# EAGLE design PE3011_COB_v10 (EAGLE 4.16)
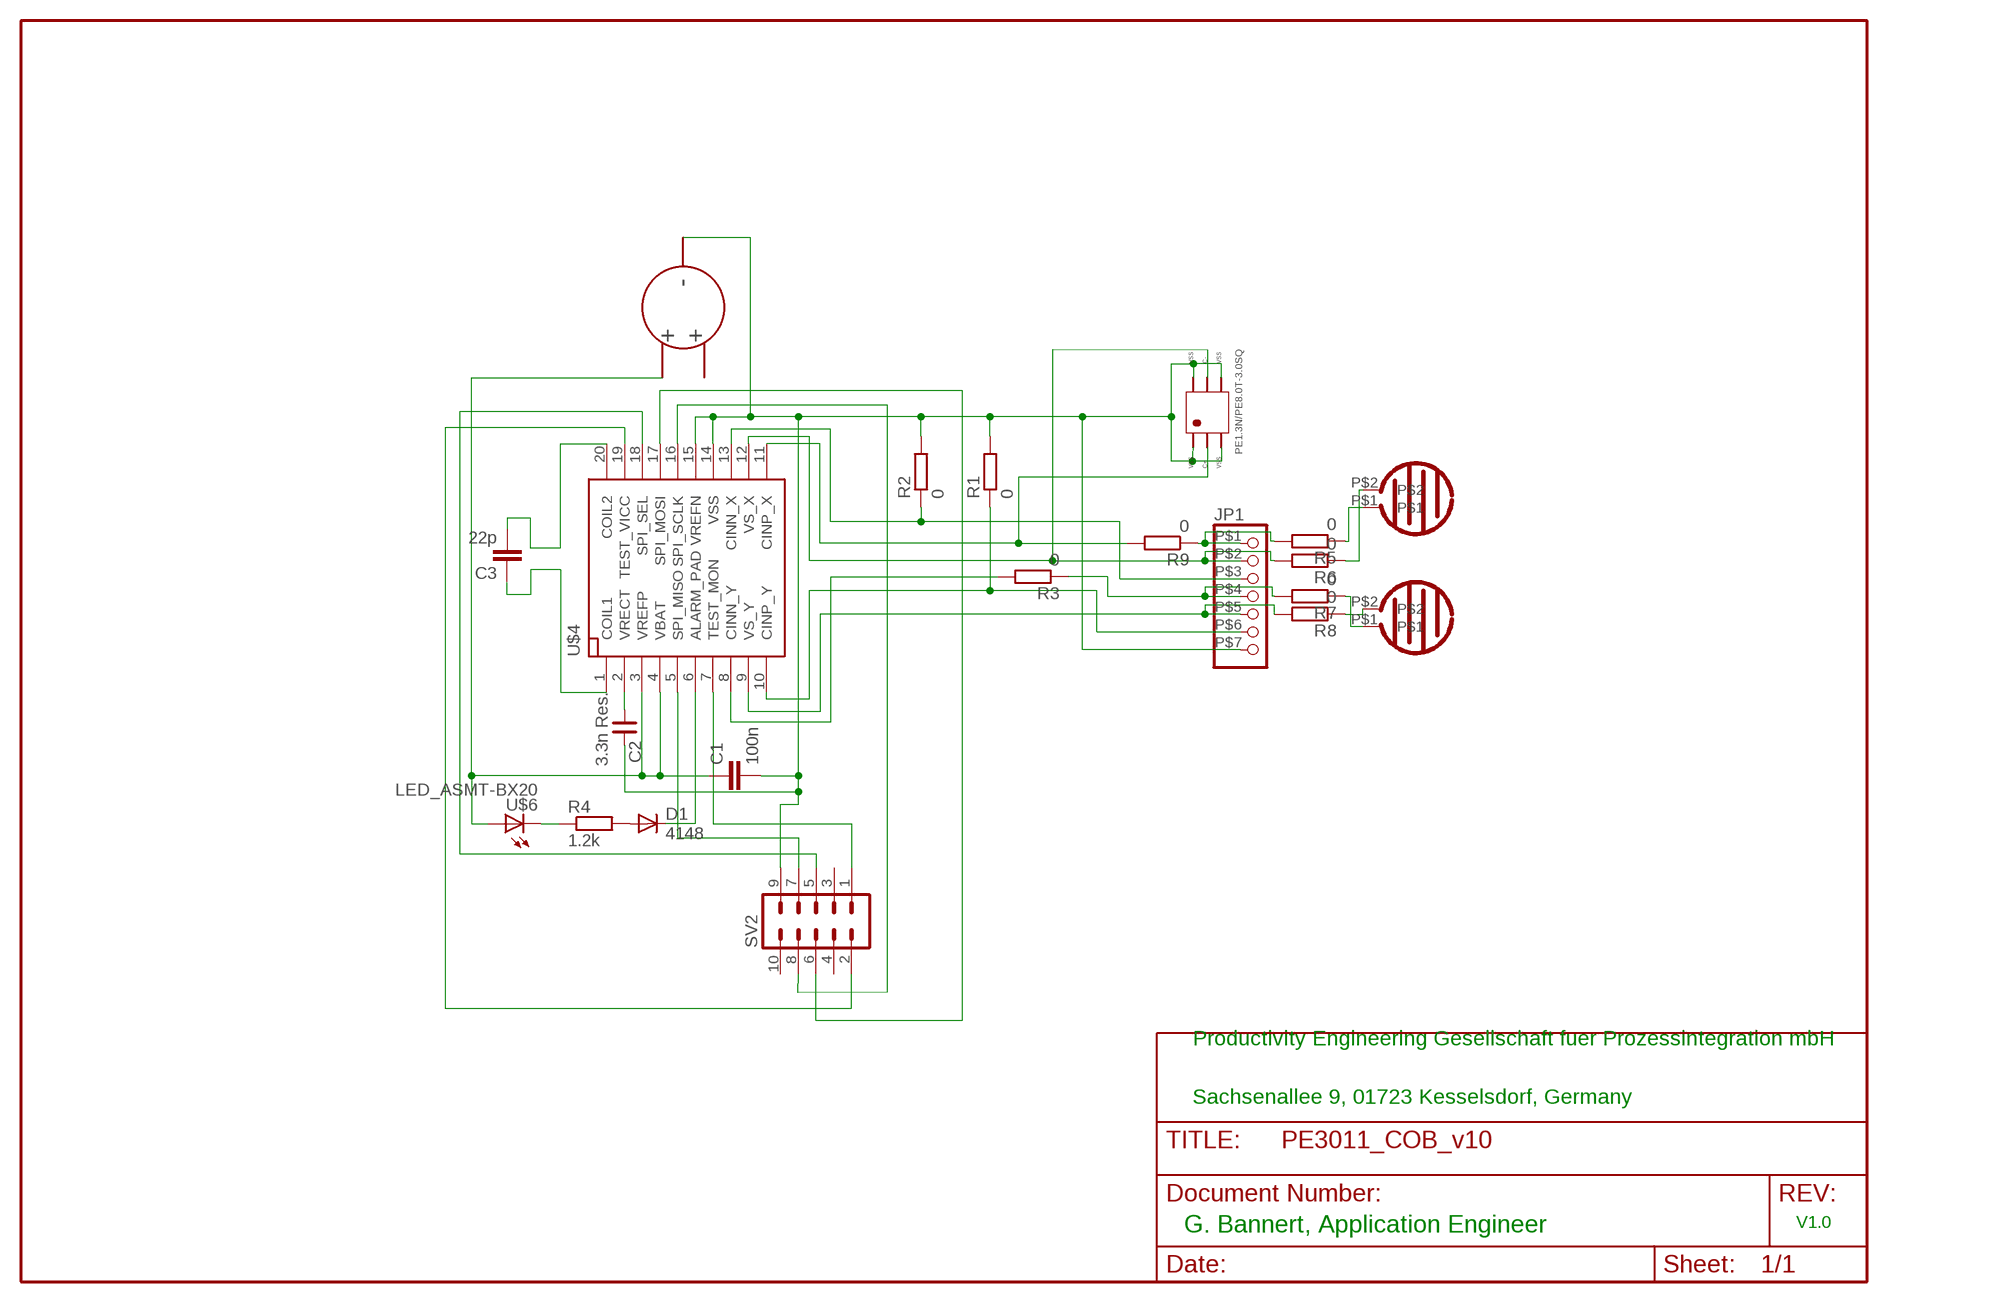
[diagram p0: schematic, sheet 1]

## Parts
C1  100n  C-EUC0805  [C0805]
C2  3.3n Res.  CNP-0402  [0402]
C3  22p  C-EUC0805  [C0805]
D1  4148  DIODE-SOD323-W  [SOD323-W]
JP1  PINHD-1X72MM  [1X07]
R1  0  R-EU_R0402  [R0402]
R2  0  R-EU_R0402  [R0402]
R3  0  R-EU_R0402  [R0402]
R4  1.2k  R-EU_R0805  [R0805]
R5  0  R-EU_R0402  [R0402]
R6  0  R-EU_R0402  [R0402]
R7  0  R-EU_R0402  [R0402]
R8  0  R-EU_R0402  [R0402]
R9  0  R-EU_R0402  [R0402]
SV2  MA05-2  [MA05-2]
U$1  TOUCH_CAP  [TOUCH_SENS]
U$2  TOUCH_CAP  [TOUCH_SENS]
U$3  MICROFAB_PRESSURESENSOR  [MICROFAB_PRESSURESENSOR]
U$4  PE3011_TSSOP20  [TSSOP20]
U$5  3002TR  [3002TR]
U$6  LED_ASMT-BX20  [LED_ASMT]

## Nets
N$1: JP1.P$2 R6.2 U$3.C- U$4.12(VS_X)
N$2: JP1.P$4 R3.1 R7.2
N$3: D1.A R4.2
N$4: R5.1 U$2.P$1
N$5: JP1.P$3 R2.1 U$4.13(CINN_X)
N$6: C3.1 U$4.1(COIL1)
N$7: R9.2 U$3.C+ U$4.11(CINP_X)
N$8: R6.1 U$2.P$2
N$9: C2.1 U$4.2(VRECT)
N$11: C1.1 U$4.3(VREFP) U$4.4(VBAT) U$5.POS_1 U$6.A
N$12: JP1.P$6 R1.1 U$4.10(CINP_Y)
N$13: SV2.5 U$4.18(SPI_SEL)
N$14: C3.2 U$4.20(COIL2)
N$15: JP1.P$1 R5.2 R9.1
N$16: SV2.2 U$4.19(TEST_VICC)
N$19: C1.2 C2.2 JP1.P$7 R1.2 R2.2 SV2.9 U$3.C_S1(CS_4) U$3.C_S2(C_S1) U$3.C_S3(C_S2) U$3.C_S4(C_S3) U$4.14(VSS) U$4.15(VREFN) U$5.NEG
N$21: SV2.7 U$4.5(SPI_MISO)
N$23: SV2.8 U$4.16(SPI_SCLK)
N$24: SV2.6 U$4.17(SPI_MOSI)
N$26: SV2.1 U$4.7(TEST_MON)
N$27: R4.1 U$6.C
N$28: D1.C U$4.6(ALARM_PAD)
N$35: R7.1 U$1.P$1
N$37: R8.1 U$1.P$2
N$38: R3.2 U$4.8(CINN_Y)
N$47: JP1.P$5 R8.2 U$4.9(VS_Y)
Unconnected: SV2.3 SV2.4 SV2.10 U$5.POS_2

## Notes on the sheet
- Productivity Engineering Gesellschaft fuer Prozessintegration mbH
- Sachsenallee 9, 01723 Kesselsdorf, Germany
- G. Bannert, Application Engineer | V1.0

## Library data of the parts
C1 C3 = rcl:C-EU: CAPACITOR, European symbol
C2 = cap-master:CNP-: NON-POLARIZED CAP
D1 = diode-1:DIODE-: DIODE
JP1 = PE5010:PINHD-1X7: PIN HEADER
R1-R9 = rcl:R-EU_: RESISTOR, European symbol
SV2 = con-lstb:MA05-2: PIN HEADER
U$1 U$2 = MeC_Bib:TOUCH_CAP
U$3 = MeC_Bib:MICROFAB_PRESSURESENSOR
U$4 = MeC_Bib:PE3011_TSSOP20
U$5 = MeC_Bib:3002TR
U$6 = MeC_Bib:LED_ASMT-BX20

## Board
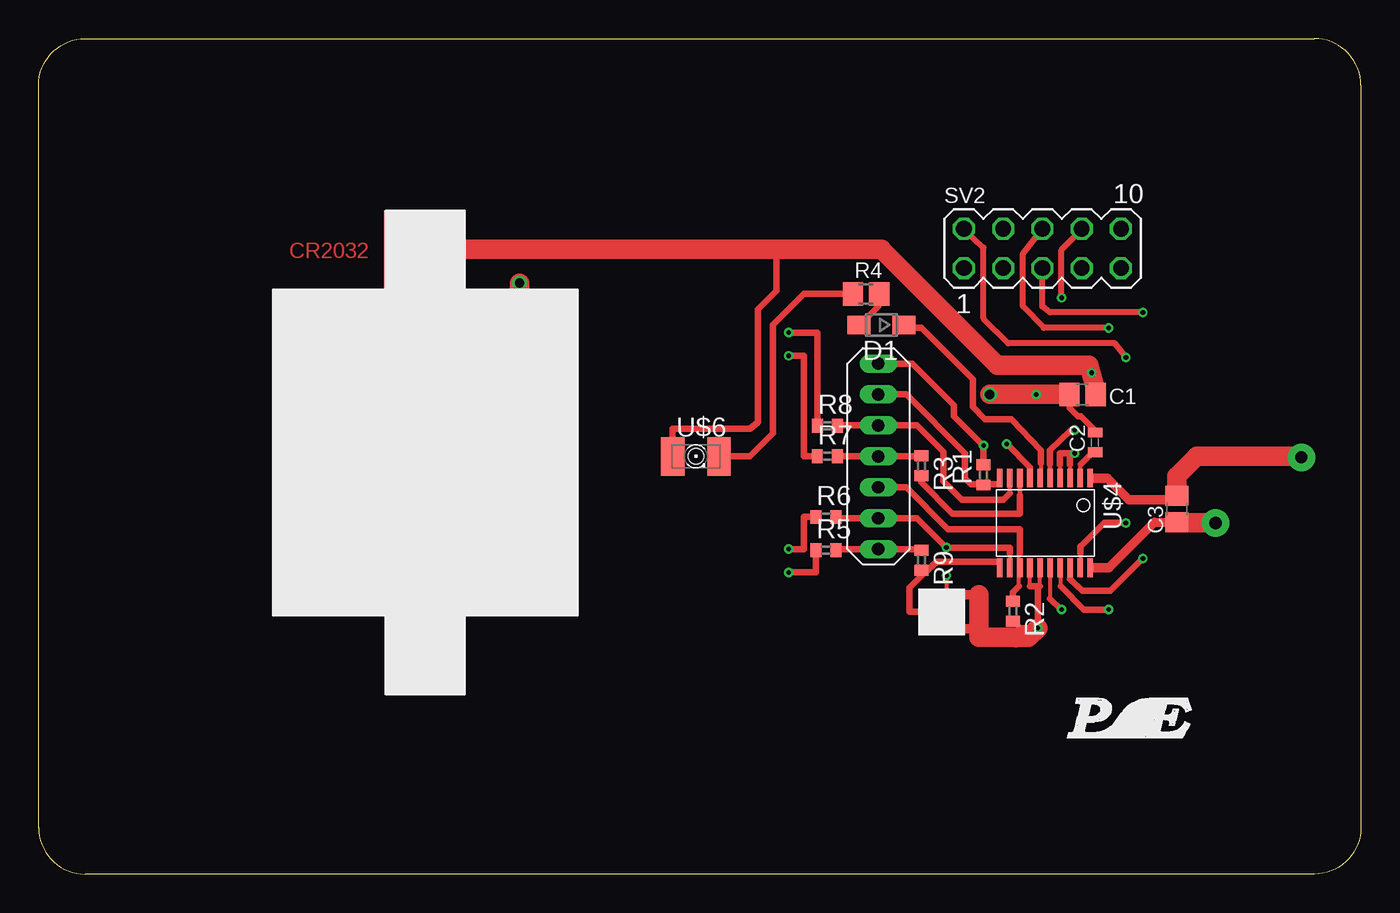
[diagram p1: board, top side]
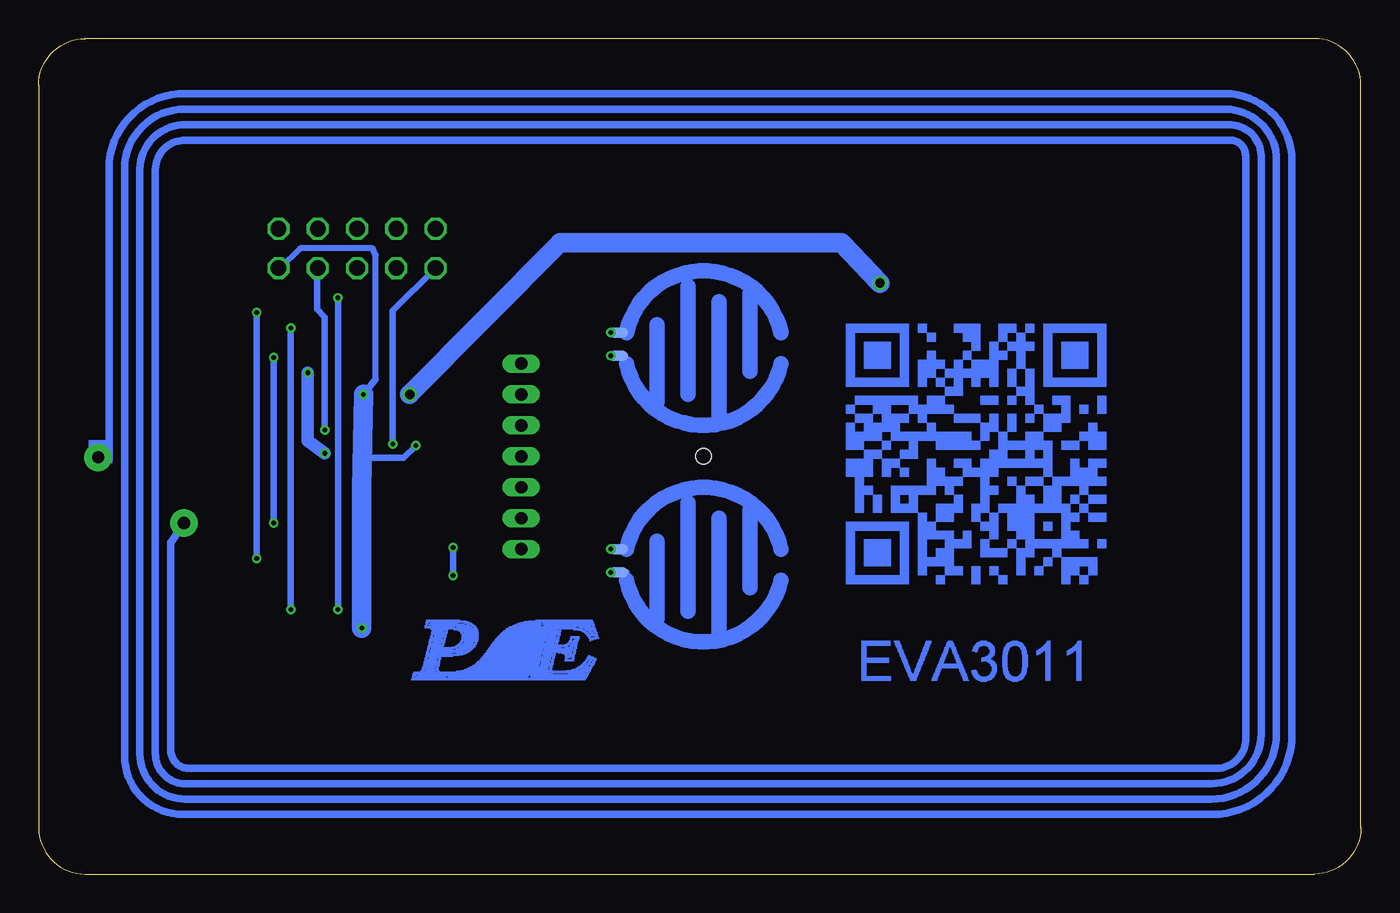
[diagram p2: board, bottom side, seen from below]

Size 85.5 x 54 mm. Coordinates in mm from the lower left corner, seen from the top.
Outline: 0,3 0,51 arc-90 3,54 82.5,54 arc-90 85.5,51 85.5,3 arc-90 82.5,0 3,0 arc-90 0,3
Copper layers (1*16): Top 0.035mm / dielectric 1.5mm / Bottom 0.035mm
Design rules "PCB-POOL": minimum track width 6mil, minimum drill 12mil, track to track 6mil, track to pad 6mil, pad to pad 6mil, via to via 6mil, smd to smd 6mil, copper to edge 20mil, drill to drill 8mil, minimum pad ring 8mil, minimum via ring 6mil, stop-mask expansion 3mil, vias tented up to drill 0mil, thermal gap 8mil
Holes 1 mm at 42.5,27

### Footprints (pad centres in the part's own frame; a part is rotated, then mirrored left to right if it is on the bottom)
C0805 = smd 1.3 x 1.5: 1 -0.85,0; 2 0.85,0
0402 = smd 0.635 x 0.94: 1 -0.635,0; 2 0.635,0
SOD323-W = smd 1.5 x 1.2: A 1.45,0; C -1.45,0
1X07 = drill 0.8 long: P$1 1,2; P$2 3,2; P$3 5,2; P$4 7,2; P$5 9,2; P$6 11,2; P$7 13,2
R0402 = smd 0.7 x 0.9: 1 -0.65,0; 2 0.65,0
R0805 = smd 1.3 x 1.5: 1 -0.85,0; 2 0.85,0
MA05-2 = drill 1.016 octagon: 1 -5.08,-1.27; 2 -5.08,1.27; 3 -2.54,-1.27; 4 -2.54,1.27; 5 0,-1.27; 6 0,1.27; 7 2.54,-1.27; 8 2.54,1.27; 9 5.08,-1.27; 10 5.08,1.27
TOUCH_SENS = smd 1.27 x 0.635: P$1 5.5,0.5; P$2 5.5,-1
MICROFAB_PRESSURESENSOR = smd 0.75 x 0.6: C+ 0.475,1.5; C- 2.525,1.5; C_S2 0.475,0.4; C_S3 2.525,0.4; C_S4 2.525,2.6 | smd 1.4 x 0.6: C_S1 0.8,2.6
TSSOP20 = smd 1.2 x 0.36: 1 -2.9,2.9; 2 -2.9,2.25; 3 -2.9,1.6; 4 -2.9,0.95; 5 -2.9,0.3; 6 -2.9,-0.35; 7 -2.9,-1; 8 -2.9,-1.65; 9 -2.9,-2.3; 10 -2.9,-2.95; 11 2.9,-2.95; 12 2.9,-2.3; 13 2.9,-1.65; 14 2.9,-1; 15 2.9,-0.35; 16 2.9,0.3; 17 2.9,0.95; 18 2.9,1.6; 19 2.9,2.25; 20 2.9,2.9
3002TR = smd 5 x 5: NEG 15.6,9.9 | smd 5.1 x 5.1: POS_1 2.56,9.79; POS_2 28.76,9.89
LED_ASMT = smd 1.5 x 2.5: A -1.5,0; C 1.5,0

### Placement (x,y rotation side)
C1  67.5,31 180 top
C2  68.31,27.91 90 top
C3  73.6,23.6 270 top
D1  54.5,35.5 180 top
JP1  56.3,20 90 top
R1  61.1,25.8 90 top
R2  62.99,16.99 270 top
R3  57.09,26.39 270 top
R4  53.5,37.5 0 top
R5  50.91,20.93 0 top
R6  50.91,23.08 0 top
R7  51,27 0 top
R8  51.01,28.98 0 top
R9  57.09,20.29 270 top
SV2  64.91,40.44 0 top
U$1  42.5,34 180 bottom
U$2  42.5,20 180 bottom
U$3  56.9,15.45 0 top
U$4  65.1,22.7 270 top
U$5  15.1,42.9 270 top
U$6  42.5,27 0 top

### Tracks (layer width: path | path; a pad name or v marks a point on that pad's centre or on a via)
N$1  (via drill 0.3)
  Top 0.2: U$3.C- 59.25,16.95 58.7,17.5
  Top 0.254: v58.7,19.3 58.7,17.5 | 62.8,20.75 U$4.12
  Top 0.406: R6.2 51.56,23 JP1.P$2 56.8,23 v58.7,21.1 62.8,21.1 62.8,20.75
  Bottom 0.406: v58.7,21.1 v58.7,19.3
N$2
  Top 0.406: 57.09,27 57.1,27 | 57.09,27 R3.1 | 54.5,27 57.09,27 | 54.5,27 JP1.P$4 | R7.2 54.5,27
N$3
  Top 0.406: D1.A 53.07,35.3 53,35.4 54.3,36.7 R4.2
N$4  (via drill 0.3)
  Top 0.406: R5.1 50.26,19.5 v48.5,19.5
  Bottom 0.406: 47.5,19.5 U$2.P$1 v48.5,19.5
N$5
  Top 0.254: 63.4,18.6 63.4,19.8 | 63.4,19.8 U$4.13 63.5,19.8 | 63.4,19.8 63.4,22.3 | 63,17.6 62.99,17.6 R2.1
  Top 0.406: JP1.P$3 56.1,25 58.8,22.3 63.4,22.3 63.45,22.3 63.45,20.75 | 63.4,18.6 63,18.2 63,17.6
N$6
  Top 0.2: 73.5,24.2 73.63,24.33 C3.1
  Top 0.305: U$4.1 68.2,25.6 | 69.05,25.6 69.1,25.6
  Top 0.61: 69.1,25.6 70.5,24.2 73.5,24.2 | 68.2,25.6 69.05,25.6
  Top 1.27: C3.1 73.6,25.7 74.9,27 81.8,27
N$7
  Top 0.254: U$4.11 62.1,19.8 62,20.2
  Top 0.406: 62,20.2 58.1,20.2 57.3,19.5 | U$3.C+ 56.3,16.95 56.3,18.5 57.3,19.5 | R9.2 57.25,19.5 57.3,19.5
N$8  (via drill 0.3)
  Top 0.406: R6.1 49.5,23.08 49.5,21 v48.5,21
  Bottom 0.406: 47.5,21 U$2.P$2 v48.5,21
N$9
  Top 0.254: C2.1 68.21,27.2 68.2,27.2 67.95,27.05 67.35,26.35 U$4.2
  Top 0.406: 67.95,27.05 67.4,26.5
N$11  (via drill 0.3)
  Top 0.254: 66.7,26.45 U$4.3 | 66.05,27.2 U$4.4
  Top 0.406: 47.7,40.4 47.7,37.7 46.5,36.5 46.5,29.2 46,28.8 41,28.8 U$6.A | 66.7,27.2 66.05,27.2 66.05,26.45 | v67,27.2 66.7,27.2 | 68.1,32.2 v68.1,32.4 | 66.7,27.2 66.7,26.45
  Top 1.27: U$5.POS_1 24.9,40.4 47.7,40.4 54.5,40.4 62,32.9 67.9,32.9 68.1,32.2 68.34,31.39 68.35,30.84 C1.1
  Bottom 0.813: v67,27.2 68.1,28 v68.1,32.4
N$12
  Top 0.254: 61.11,25.2 R1.1
  Top 0.305: 61.11,25.2 61.4,25.2 | 62.1,25.2 62.15,25.2 U$4.10
  Top 0.406: JP1.P$6 56.1,31 59.9,27.2 59.9,25.6 60.3,25.2 61.11,25.2 | 61.4,25.2 62.1,25.2
N$13  (via drill 0.3)
  Top 0.2: 64.9,39.2 64.91,39.19 SV2.5
  Top 0.254: 67.6,18.3 66.7,19.2 U$4.18
  Top 0.4: 64.9,39.2 64.9,36.7 65.4,36.3 v71.4,36.3
  Top 0.406: v71.4,20.4 69.3,18.3 67.6,18.3
  Bottom 0.406: v71.4,20.4 v71.4,36.3
N$14  (via drill 0.8 pad 1.78)
  Top 0.2: 73.7,22.7 73.7,22.8
  Top 0.305: U$4.20 68.15,19.8
  Top 0.61: 73.7,22.7 72.15,22.75 69.2,19.8 68.15,19.8
  Top 1.27: C3.2 73.7,22.7 arc2 v76.1,22.7
  Bottom 0.5: v76.1,22.7 76.85,21.55
N$15
  Top 0.406: 54.5,21 JP1.P$1 51.56,21 | 57.29,21 57.3,21 | 57.29,21 R9.1 | R5.2 51.56,21 | 51.56,21 57.29,21
N$16  (via drill 0.3)
  Top 0.2: 59.8,41.7 59.81,41.71 SV2.2
  Top 0.254: U$4.19 67.35,19.9 67.4,19.9 67.4,21.2
  Top 0.4: 59.8,41.7 61.1,40.5 61.1,35.9 62.7,34.3 69.6,34.3 v70.3,33.4
  Top 0.406: v70.3,22.7 68.9,22.7 67.4,21.2 67.35,21.2 67.35,20.75
  Bottom 0.406: v70.3,22.7 v70.3,33.4
N$19  (via drill 0.3, 0.6)
  Top 0.2: 57.38,15.88 U$3.C_S2 58.3,16.5 | 59.4,18.05 59.42,18.02 U$3.C_S4 | U$3.C_S1 58.3,18 58.3,16.5 | U$3.C_S3 59.4,15.8 58.3,16.5
  Top 0.254: 64.75,18.6 U$4.15 | 64.1,18.6 U$4.14
  Top 0.305: 63.1,16.3 63.1,16.34 R2.2
  Top 0.406: 64.5,18.6 64.1,18.6 | 64.5,18.6 64.75,18.6 | JP1.P$7 56.5,33 59.2,30.3 59.2,29.6 v61.1,27.7 R1.2 | 63.1,16.3 63.5,15.9 v64.6,15.9 64.6,18.6 64.5,18.6 | C2.2 68.21,28.79 67.4,29.6 67.2,29.6 66.7,30.1 66.7,31 C1.2
  Top 0.61: 60.8,18.05 59.4,18.05 | 60.8,15.85 U$3.C_S3
  Top 1.27: U$5.NEG 31.11,30.61 v31.1,38.2 | 60.8,15.85 60.8,18.05 60.8,15.3 63,15.3 63.18,15.28 64,15.3 v64.6,15.9 | C1.2 v64.5,31 v61.5,31
  Bottom 0.2: 69.93,39.17 SV2.9 | 64.6,24.9 64.3,24.9
  Bottom 0.4: 69.93,39.17 68.6,40.45 63.9,40.45 63.7,40 63.7,32
  Bottom 0.406: v64.5,31 63.7,32 | v61.1,27.7 61.9,26.9 64.3,26.9 64.3,24.9
  Bottom 1.27: v64.6,15.9 64.6,24.9 v64.5,31 | v31.1,38.2 33.6,40.8 51.8,40.8 v61.5,31
N$21  (via drill 0.3)
  Top 0.305: U$4.5 65.4,26.5
  Top 0.406: v67,28.7 66.75,28.7 65.4,27.4 65.4,26.5
  Bottom 0.2: 67.43,39.17 67.4,39.2 | 67.43,39.17 SV2.7 | 67.5,39.1 67.43,39.17
  Bottom 0.406: v67,28.7 67,36 67.5,36.5 67.5,39.1
N$23  (via drill 0.3)
  Top 0.2: 67.5,41.7 67.49,41.71 SV2.8
  Top 0.254: U$4.16 65.4,17.8
  Top 0.4: v66.15,37.25 66.15,40.35 67.5,41.7
  Top 0.406: 65.4,17.8 v66.15,17.1
  Bottom 0.406: v66.15,17.1 v66.15,37.25
N$24  (via drill 0.3)
  Top 0.254: U$4.17 66.1,19.8 66.1,18.6
  Top 0.4: SV2.6 63.65,40.1 63.65,36.7 65,35.3 v69.2,35.3
  Top 0.406: 66.1,18.6 67.6,17.1 v69.2,17.1
  Bottom 0.2: SV2.6 64.91,41.69
  Bottom 0.406: v69.2,17.1 v69.2,35.3
N$26  (via drill 0.3)
  Top 0.305: 64.1,26.3 U$4.7
  Top 0.406: v62.6,27.8 64.1,26.3
  Bottom 0.4: 59.8,39.2 SV2.1 62.6,36.4
  Bottom 0.406: v62.6,27.8 62.6,36.4
N$27
  Top 0.406: R4.1 49.5,37.5 47.5,35.5 47.5,28.5 46,27 U$6.C
N$28
  Top 0.254: U$4.6 64.8,25.6 64.8,26.55
  Top 0.406: D1.C 56,35.31 56,35.3 57.1,35.3 60.4,32 60.4,30.2 61.2,29.4 62.9,29.4 64.8,27.4 64.8,26.55
N$29
  Bottom 0.5: 80.95,26.8 80.95,45.63 arc90 76.03,50.45 8.77,50.45 arc90 4.45,46.13 4.45,9.01 arc90 9.61,3.85 76.15,3.85
N$30
  Top 0.406: 67.45,18.35 67.5,18.3 66.7,19.05
N$35  (via drill 0.3)
  Top 0.406: R7.1 49.5,27 49.5,33.5 v48.5,33.5
  Bottom 0.406: v48.5,33.5 U$1.P$1
N$37  (via drill 0.3 pad 0.3)
  Top 0.406: R8.1 50.36,35 v48.5,35
  Bottom 0.406: v48.5,35 U$1.P$2
N$38
  Top 0.305: 63.45,24.5 U$4.8
  Top 0.406: 63.45,24.5 63.45,23.3 59.1,23.3 57.09,25.31 R3.2
N$47
  Top 0.254: 62.8,24.6 U$4.9
  Top 0.406: 62.8,24.6 62.4,24.2 59.7,24.2 58.5,25.4 58.5,27.3 56.8,29 54.5,29 | 54.5,29 JP1.P$5 | R8.2 51.66,29 54.5,29
N$102  (via drill 0.8 pad 1.78)
  other vias: 81.65,26.94
N$107
  Bottom 0.5: 76.15,3.85 arc90 79.95,7.65 79.95,45.62 arc90 76.03,49.44 8.75,49.44 arc90 5.45,46.14 5.45,9.07 arc90 9.68,4.84 76.05,4.84 arc90 78.95,7.75 78.95,45.58 arc90 75.99,48.44 8.55,48.44 arc90 6.45,46.44 6.45,9.04 arc90 9.65,5.84 76.01,5.84 arc90 77.95,7.78 77.95,45.55 arc90 75.96,47.44 8.45,47.44 arc90 7.45,46.44 7.45,8.64 arc90 9.45,6.84 75.81,6.84 arc90 76.95,7.98 76.95,21.44
(copper drawn outside any net)
  shapes: Bottom area x2843

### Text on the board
Top: CR2032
